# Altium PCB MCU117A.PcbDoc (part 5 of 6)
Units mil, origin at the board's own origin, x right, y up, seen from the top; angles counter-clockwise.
Board outline 2300 x 6749.64 mil, 6 copper layers (Top Signal, GND, Middle Signal, PWR, GND2, Bottom Signal), stack 61.64 mil thick; 424 components, 343 nets, 1563 pads, 921 vias.
Unrouted connection lines stored in the file: 4.
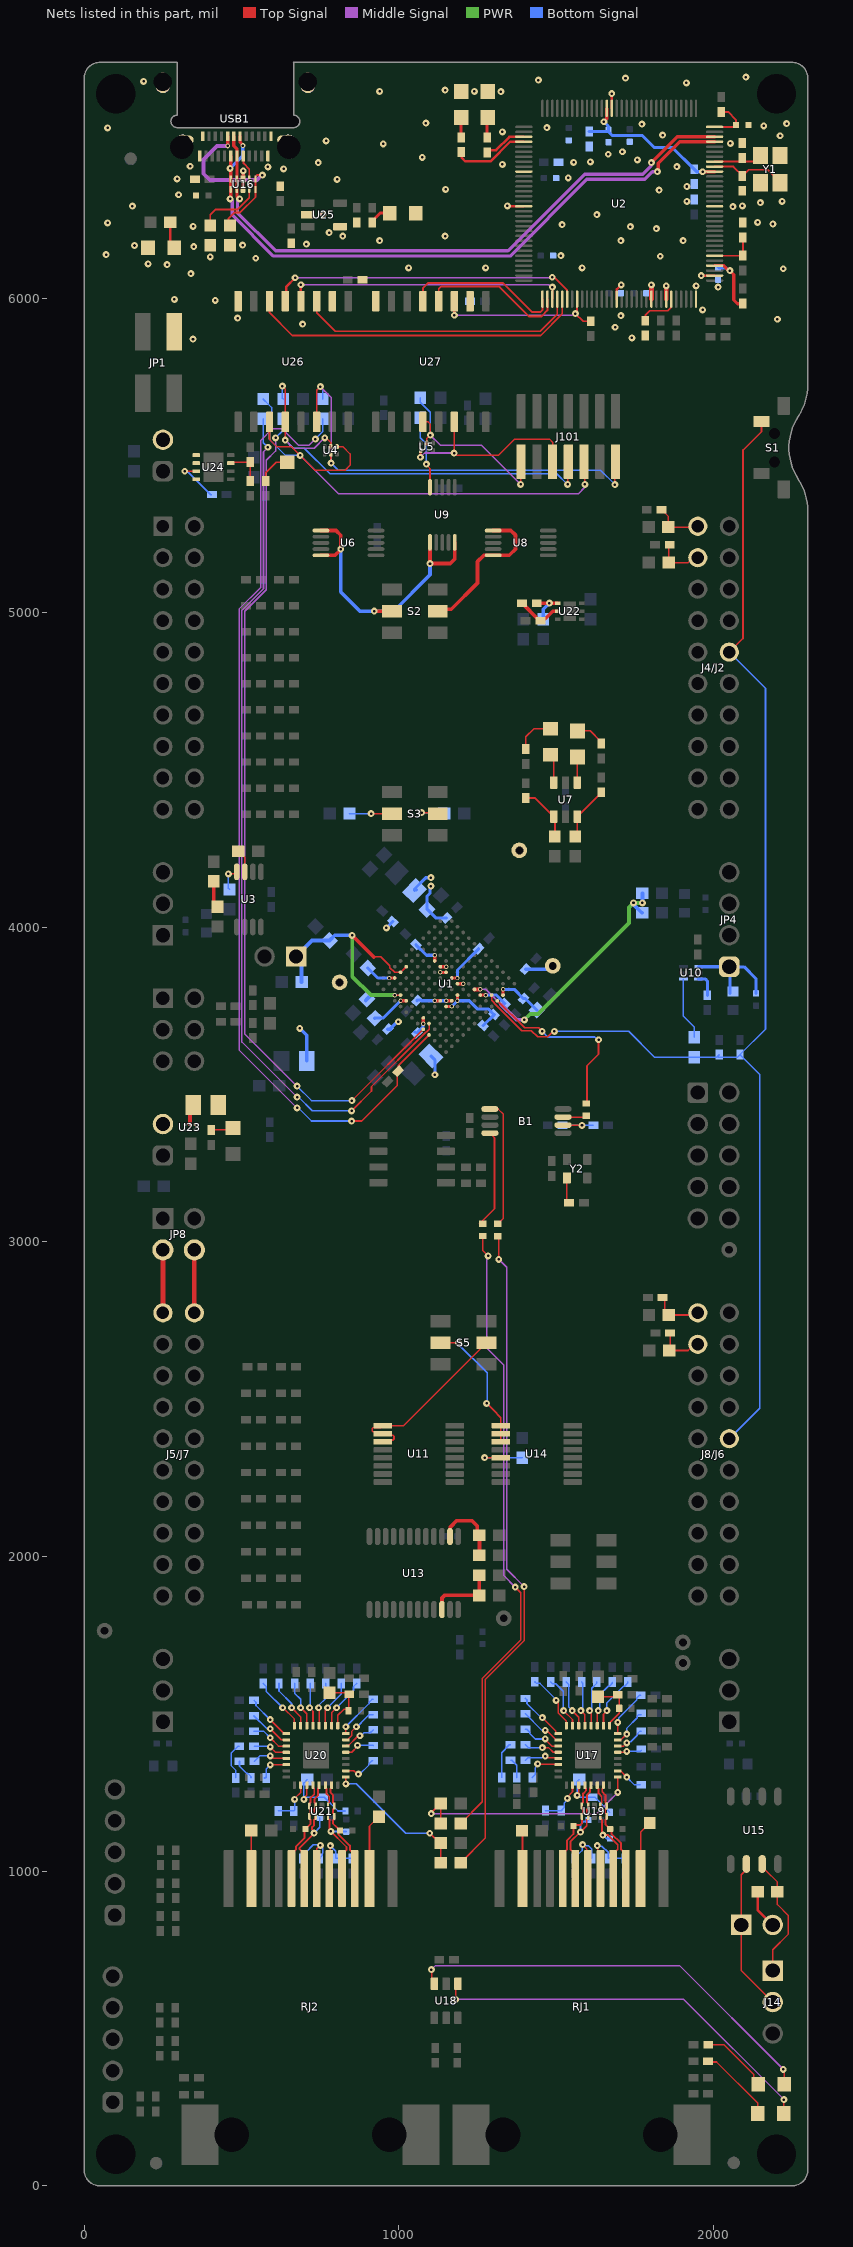
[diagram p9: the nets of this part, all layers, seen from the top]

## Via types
v1: diameter 22, hole 8, Top Signal to Bottom Signal, tented both sides, 821 vias
v2: diameter 14, hole 8, Top Signal to Bottom Signal, tented both sides, 82 vias
v3: diameter 19.68, hole 7.87, Top Signal to Bottom Signal, tented top, 14 vias
v4: diameter 15.75, hole 7.87, Top Signal to Bottom Signal, tented both sides, 2 vias
v5: diameter 19.68, hole 7.87, Top Signal to Bottom Signal, 2 vias

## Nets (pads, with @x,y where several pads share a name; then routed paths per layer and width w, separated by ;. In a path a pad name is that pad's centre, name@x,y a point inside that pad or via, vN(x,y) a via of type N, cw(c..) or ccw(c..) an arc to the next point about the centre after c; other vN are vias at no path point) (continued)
MCU_TDI: R99.1 U1.N9 | length 2754.5
  Top Signal w5: v1(850.28,3449.19) 850.83,3449.19 U1.N9@1077.57,3675.93
  Middle Signal w5: v1(608.14,5555.59) 608.14,5513.85 578.63,5484.34 578.63,5072.64 510.11,5004.11 510.11,3661.22 v1(676.18,3495.14)
  Bottom Signal w5: v1(608.14,5555.59) 632.11,5579.55 R99.1@632.11,5616.01 ; v1(676.18,3495.14) 722.13,3449.19 v1(850.28,3449.19)
MCU_TDI_INT: J101.8 R99.2 U4.5 U26.12 | length 1436.3
  Top Signal w5: v1(629.53,5720.16) 638.77,5710.92 v1(638.77,5548.46) ; v1@764.28,5560 783.64,5540.64 U4.5@783.64,5527.8 ; v1(1535.98,5407.41) 1535.98,5477.01 J101.8@1538.46,5479.49
  Middle Signal w5: v1(638.77,5548.46) 664.31,5522.92 730.89,5522.92 763.56,5555.59 v1(764.29,5555.59)
  Bottom Signal w5: v1(629.53,5720.16) 629.53,5681.57 R99.2@632.11,5679 ; v1(638.77,5548.46) 664.31,5522.92 699.57,5522.92 781.1,5441.4 1501.99,5441.4 v1(1535.98,5407.41)
MCU_TDO: R100.1 U1.M9 | length 2839.5
  Top Signal w4: 1077.57,3658.38 1095.67,3676.48 U1.M9@1095.67,3694.02
  Top Signal w5: v1(849.98,3416.58) 913.01,3479.6 913.01,3493.82 1077.57,3658.38
  Middle Signal w5: v1(583.65,5525.58) 569.63,5511.57 569.63,5076.37 501.11,5007.84 501.11,3635.5 v1(676.18,3460.43)
  Bottom Signal w5: R100.1@569.11,5616.01 569.11,5540.13 v1(583.65,5525.58) ; v1(676.18,3460.43) 680.61,3460.43 724.46,3416.58 v1(849.98,3416.58)
MCU_TDO_INT: J101.6 R100.2 U4.4 U26.11 | length 1751.8
  Top Signal w5: U26.11@588.77,5606.07 588.77,5550.64 612.67,5526.73 659.19,5526.73 v1(686.22,5499.71) 733.3,5452.63 829.09,5452.63 844.81,5468.34 844.81,5504.17 821.18,5527.8 U4.4@803.33,5527.8 ; J101.6@1588.46,5479.49 1590.82,5477.12 v1@1590.82,5398.49
  Middle Signal w5: v1(686.22,5499.71) 807.8,5378.12 1570.45,5378.12 v1@1590.82,5398.49
  Bottom Signal w5: R100.2@569.11,5679 569.11,5678.02 585.31,5661.81 585.84,5661.81 595.31,5652.35 595.31,5593.22 588.77,5586.68 588.77,5550.64 639.7,5499.71 v1(686.22,5499.71)
  other v1: 1590.82,5407.41
MCU_TMS: R44.1 R97.1 U1.N10 | length 3103.8
  Top Signal w4: R44.1@997.83,3542.69 997.83,3560 U1.N10@1095.67,3657.83
  Top Signal w5: v1(849.58,3384.3) 881.97,3384.3 995.35,3497.67 R44.1@995.35,3542.69
  Middle Signal w5: v1(676.18,3425.71) 492.11,3609.79 492.11,5011.57 560.63,5080.09 560.63,5547.11 598.55,5585.04 627.73,5585.04 680.85,5531.92 714.63,5531.92 v1(734.38,5551.67)
  Bottom Signal w5: v1(676.18,3425.71) 680.61,3425.71 722.02,3384.3 v1(849.58,3384.3) ; v1(734.38,5551.67) 758.11,5575.39 R97.1@758.11,5616.01
MCU_TMS_INT: J101.2 R97.2 U4.2 U26.14 | length 1450.3
  Top Signal w5: U26.14@738.77,5606.07 738.77,5706.78 v1(750.34,5718.35) ; U4.2@783.64,5504.17 783.64,5476.02 v1(784.69,5474.98) ; v1(1686.58,5406.94) 1686.58,5477.61 J101.2@1688.46,5479.49
  Middle Signal w5: v1(750.34,5718.35) 784.69,5684 v1(784.69,5474.98)
  Bottom Signal w5: v1(750.34,5718.35) 758.11,5710.58 R97.2@758.11,5679 ; v1(784.69,5474.98) 807.26,5452.41 1641.11,5452.41 v1(1686.58,5406.94)
MCU_TXD: R171.1 U9.10 | length 234
  Top Signal w5: v1(1087.05,5472.39) 1087.05,5469.75 1098.81,5457.99 U9.10@1098.81,5398.49
  Bottom Signal w5: R171.1@1068.17,5619.76 1068.17,5556.14 1087.05,5537.26 v1(1087.05,5472.39)
MCU_TXD_INT: J101.14 R171.2 U5.5 U27.12 | length 648.2
  Top Signal w5: U27.12@1076.45,5606.07 1093.63,5606.07 1099.88,5599.81 v1(1099.88,5564.14) 1088.9,5553.15 U5.5@1088.9,5538.62 ; v1(1387,5407.41) 1387,5478.03 J101.14@1388.46,5479.49
  Middle Signal w5: v1(1099.88,5564.14) 1131.52,5532.5 1261.91,5532.5 v1(1387,5407.41)
  Bottom Signal w5: R171.2@1068.17,5682.75 1068.17,5668.75 1099.88,5637.03 v1(1099.88,5564.14)
NetB1_2: B1.2 R24.2 R26.2 | length 153.9
  Top Signal w5: B1.2@1521.54,3371.33 1580.98,3371.33 v1(1581.94,3370.36)
  Bottom Signal w5: R26.2@1524.71,3370.36 v1(1581.94,3370.36) R24.2@1617.86,3370.36
NetB1_3: B1.3 R20.1 | length 63.3
  Top Signal w5: B1.3@1535.8,3395.95 1587.25,3395.95 R20.1@1595.63,3404.34
NetB1_5: B1.5 R22.1 | length 405.1
  Top Signal w5: B1.5@1289.26,3422.51 1315.26,3422.51 1332.16,3405.61 1332.16,3075.29 R22.1@1314.54,3057.67
NetB1_8: B1.8 R21.1 | length 314
  Top Signal w5: R21.1@1255.95,3057.67 1303.89,3105.61 1303.89,3331.11 B1.8@1289.26,3345.74
NetC1_1: C1.1 J4/J2.39 R2.1 | length 156.9
  Top Signal w5: C1.1@1860.91,5215.41 1857.45,5211.95 1857.45,5167.36 R2.1@1857.45,5158.98 1919.17,5158.98 1934.83,5174.64 J4/J2.39@1949.99,5174.64
NetC2_1: C2.1 J4/J2.40 R1.1 | length 158.9
  Top Signal w5: C2.1@1834.95,5327.3 1856.61,5305.65 R1.1@1856.61,5271.89 1947.24,5271.89 J4/J2.40@1949.99,5274.64
NetC3_1: C3.1 J8/J6.80 R3.1 | length 158.4
  Top Signal w5: C3.1@1838.31,2823.34 1845.24,2816.41 1845.24,2780.65 R3.1@1857.99,2767.89 1943.24,2767.89 J8/J6.80@1949.99,2774.64
NetC4_1: C4.1 J8/J6.79 R4.1 | length 152.8
  Top Signal w5: R4.1@1859.01,2655 1862.24,2658.23 C4.1@1862.24,2710.54 ; R4.1@1862.24,2655 1918.8,2655 1938.45,2674.64 J8/J6.79@1949.99,2674.64
NetC52_1: C52.1 R66.1 | length 77.4
  Top Signal w12: C52.1@411.27,4137.33 411.27,4081.81 424.62,4068.46 R66.1@424.62,4065.51
NetC53_1: C53.1 U3.4 | length 80.3
  Top Signal w5: v1(458.02,4169.71) 477.88,4169.71 U3.4@484.52,4176.35
  Bottom Signal w5: v1(458.02,4169.71) 458.02,4124.11 C53.1@461.88,4120.25
NetC87_2: C87.2 C88.2 RJ1.5 | length 225
  Top Signal w5: v1(1630.52,1081.53) 1631.86,1080.19 1631.86,985.5 RJ1.5@1640.79,976.57
  Bottom Signal w4: v1(1630.52,1081.53) 1632.05,1080 1645.03,1080 1665.01,1060.03 1665.01,1042.6 C88.2@1666.99,1040.62 C87.2@1719.18,1040.62
NetC89_1: C89.1 C90.1 U17.2 | length 142.6
  Top Signal w5: v1(1535.78,1231.61) 1535.78,1236.21 1551.78,1252.21 U17.2@1551.78,1270.27
  Bottom Signal w5: C89.1@1465.98,1192.38 C90.1@1515.72,1192.38 1525.04,1201.69 1525.04,1216.27 1535.78,1227.01 v1(1535.78,1231.61)
NetC95_2: C95.2 C96.2 RJ1.6 | length 232.5
  Top Signal w5: v1(1583.95,1084.27) 1596.53,1071.69 1596.53,980.68 RJ1.6@1600.64,976.57
  Bottom Signal w5: C96.2@1560.99,1040.62 1560.99,1044.56 1582.2,1065.77 1582.2,1082.51 v1(1583.95,1084.27) 1587,1081.22 1602.45,1081.22 1612.99,1070.68 C95.2@1612.99,1040.62
NetC97_1: C97.1 C98.1 R131.2 U17.3 | length 214.8
  Top Signal w4: v1(1566.18,1241) 1571.46,1246.29 U17.3@1571.46,1273.71
  Bottom Signal w5: C97.1@1572.73,1291.13 1566.18,1284.58 v1(1566.18,1241) 1572.51,1234.67 C98.1@1615.91,1234.67 1622.93,1234.67 R131.2@1670.78,1186.82
NetC99_1: C99.1 C100.1 R134.1 U17.17 | length 176.8
  Top Signal w5: C99.1@1633.17,1554.85 1689.95,1554.85 C100.1@1695.49,1560.38 1700.18,1555.69 R134.1@1700.18,1517.82 1700.18,1502.13 1669.89,1471.84 U17.17@1669.89,1462.69
NetC102_2: C102.2 C104.2 RJ2.5 | length 206
  Top Signal w4: RJ2.5@779.08,976.57 782.11,979.6 v1(782.11,1081.08)
  Bottom Signal w5: v1(782.11,1081.08) 799.42,1063.77 C104.2@799.42,1040.62 C102.2@852,1040.62
NetC105_1: C105.1 C106.1 U20.2 | length 139.9
  Top Signal w5: v1(668.56,1228.43) 668.56,1231.02 687.82,1250.28 687.82,1273.53 U20.2@687.63,1273.71
  Bottom Signal w5: C105.1@617,1191.97 C106.1@666,1191.97 668.56,1194.53 v1(668.56,1228.43)
NetC111_2: C111.2 C112.2 RJ2.6 | length 238.8
  Top Signal w4: RJ2.6@738.92,976.57 738.92,1070.86 v1(750.16,1082.1)
  Bottom Signal w5: C112.2@695,1040.62 703.83,1049.46 703.83,1059.83 727.72,1083.72 748.54,1083.72 v1(750.16,1082.1) 750.16,1081.08 757.49,1073.75 757.49,1056.71 756.81,1056.04 756.81,1050.43 C111.2@747,1040.62
NetC113_1: C113.1 C114.2 R166.2 U20.3 | length 268.6
  Top Signal w5: v1(698.18,1228.43) 698.18,1233.3 707.32,1242.44 U20.3@707.32,1273.71
  Bottom Signal w5: C113.1@708.65,1291.13 698.18,1280.66 v1(698.18,1228.43) 704.57,1234.83 762.78,1234.83 806.21,1191.4 R166.2@830.05,1191.4
NetC115_1: C115.1 C116.2 R168.1 U20.17 | length 194.7
  Top Signal w4: R168.1@840.21,1510.09 840.21,1517.22 840.21,1557.91 C116.2@842.32,1560.03
  Top Signal w5: C115.1@779.1,1567.08 837.96,1567.08 C116.2@842.32,1562.72 C116.2@842.32,1560.03 ; U20.17@805.74,1462.69 805.74,1495.33 825.35,1514.94 837.92,1514.94 R168.1@840.21,1517.22
NetC123_1: C123.1 U24.3 | length 152.7
  Top Signal w4: v1(319.48,5449.51) U24.3@355.62,5449.51
  Bottom Signal w4: v1(319.48,5449.51) 322.92,5446.06 330.86,5446.06 401.43,5375.49 C123.1@405.37,5375.49
NetC125_1: C125.1 U10.3 | length 76.8
  Bottom Signal w10: U10.3@1951.62,3835.32 1974.65,3835.32 1980.51,3829.46 C125.1@1980.51,3783.93
NetC131_2: C131.2 R164.2 U2.96 | length 144.3
  Top Signal w6: U2.96@2003.34,6543.74 2065.55,6543.74 C131.2@2071.32,6549.5 2071.32,6566.3 2046.24,6591.38 R164.2@2024.59,6591.38
NetC142_1: C142.1 C143.2 C144.1 U2.87 U2.115 | length 531.6
  Top Signal w10: v1(1651.4,6560.23) 1660.82,6569.65 U2.115@1660.82,6602.79 ; v1(1965.27,6401.41) U2.87@2003.93,6401.41
  Bottom Signal w10: C144.1@1604.32,6529.43 C143.2@1661.18,6529.43 ; v1(1651.4,6560.23) 1666.29,6545.33 C143.2@1666.29,6534.55 1666.29,6528.4 1678.15,6516.54 1773.25,6516.54 1811.38,6478.42 1869.21,6478.42 C142.1@1938.48,6409.14 1946.21,6401.41 v1(1965.27,6401.41)
NetC145_2: C145.2 R177.1 U2.68 | length 230.3
  Top Signal w10: U2.68@2003.34,6102.79 2032.75,6102.79 2048.5,6087.04 v1(2051.75,6087.04) 2064.13,6074.66 2064.13,5993.66 2076.17,5981.61 R177.1@2093.65,5981.61
  Bottom Signal w10: C145.2@2014.52,6099.37 2017.78,6096.11 2039.43,6096.11 2048.5,6087.04 v1(2051.75,6087.04)
NetC146_1: C146.1 U2.89 Y1.3 | length 153.4
  Top Signal w6: U2.89@2003.34,6433.5 2129.24,6433.5 Y1.3@2148.69,6452.95
NetC147_1: C147.1 U2.88 Y1.1 | length 249.7
  Top Signal w6: U2.88@2003.34,6417.75 2063.14,6417.75 2094.01,6386.89 2094.01,6389.72 2111.84,6407.56 2172.57,6407.56 2211.69,6368.44 Y1.1@2211.69,6366.33
NetD11_1: D11.1 U18.6 | length 1358.4
  Top Signal w5: v1(1103,687) 1104.26,685.74 1104.26,650.55 U18.6@1112.82,641.99 ; v1(2221.58,370.21) 2224.65,367.15 D11.1@2224.65,322.85
  Middle Signal w5: v1(1103,687) 1116.12,700.12 1891.68,700.12 v1(2221.58,370.21)
NetD11_2: D11.2 R137.1 | length 220.7
  Top Signal w5: R137.1@1983.1,448.55 2032.96,448.55 2127.82,353.68 2127.82,337 D11.2@2141.97,322.85
NetD12_1: D12.1 U18.4 | length 1271.1
  Top Signal w5: v1(1180.62,592.91) 1180.62,634.99 U18.4@1187.62,641.99 ; v1(2223.58,274.21) 2223.58,230.14 D12.1@2223.65,230.08
  Middle Signal w5: v1(1180.62,592.91) 1904.88,592.91 v1(2223.58,274.21)
NetD12_2: D12.2 R138.2 | length 245.7
  Top Signal w5: R138.2@1982.94,396.16 1985.54,393.56 2009.72,393.56 2140.97,262.31 D12.2@2140.97,230.08
NetJ5/J7_41: J5/J7.41 JP8.3 | length 200
  Top Signal w15: J5/J7.41@249.99,2774.64 JP8.3@249.99,2974.64
NetJ5/J7_61: J5/J7.61 JP8.4 | length 200
  Top Signal w15: J5/J7.61@349.99,2774.64 JP8.4@349.99,2974.64
NetJ14_1: J14.1 R11.2 U15.7 | length 396.1
  Top Signal w5: U15.7@2154.49,1023.02 2154.49,1010.52 2161.71,1003.3 2165.04,1003.3 2202.99,965.35 R11.2@2202.99,934.65 2202.99,893.86 2237.99,858.85 2237.99,800.31 2188.29,750.61 J14.1@2188.29,684.07
NetJ14_2: J14.2 JP9.1 U15.6 | length 487.3
  Top Signal w5: U15.6@2104.49,1023.02 2104.49,1005.62 2087.99,989.12 JP9.1@2087.99,829.31 2087.99,684.36 J14.2@2188.29,584.07
NetJ16_2: J16.2 U24.1 U24.2 U24.4
NetJ17_2: J17.2 L4.1 U23.A1 U23.C1
NetJP9_2: JP9.2 R11.1 | length 125.2
  Top Signal w8: R11.1@2140,934.65 2140,877.31 JP9.2@2187.99,829.31
NetL4_2: L4.2 U23.B1 | length 66.5
  Top Signal w6: L4.2@335.75,3424.75 L4.2@346,3435
  Top Signal w12: U23.B1@335.75,3372.75 L4.2@335.75,3424.75
NetLED1_2: LED1.2 R69.1 | length 85.6
  Top Signal w8: R69.1@273.63,6240.51 273.63,6171.56 LED1.2@285.43,6159.76
NetLED3_2: LED3.2 R82.1 | length 71.2
  Top Signal w5: R82.1@396,3356.62 463.56,3356.62 LED3.2@466.15,3359.21
NetLED4_1: LED4.1 U7.6 | length 92.8
  Top Signal w5: LED4.1@1482.15,4548.47 1492.15,4538.47 U7.6@1492.15,4459.8
NetLED4_2: LED4.2 R12.1 | length 128
  Top Signal w5: R12.1@1403.55,4566.77 1403.55,4605.65 1429.06,4631.15 LED4.2@1482.15,4631.15
NetLED5_1: LED5.1 R13.1 | length 88.7
  Top Signal w5: LED5.1@1568.2,4624.45 1607.88,4624.45 R13.1@1642.55,4589.77
NetLED5_2: LED5.2 U7.4 | length 82.5
  Top Signal w5: U7.4@1566.96,4459.8 1566.96,4540.53 LED5.2@1568.2,4541.77
NetLED6_2: LED6.2 R90.2 | length 107.9
  Top Signal w5: R90.2@576.92,5418.89 576.92,5444.48 610.5,5478.07 LED6.2@645.34,5478.07
NetLED7_2: LED7.2 R96.2 | length 68.8
  Top Signal w10: R96.2@910.18,6239.81 940.77,6270.39 LED7.2@966.33,6270.39
NetLED8_1: LED8.1 R172.1 | length 64.5
  Top Signal w10: R172.1@1280.25,6509.98 1280.25,6571.67 LED8.1@1282.24,6573.66
NetLED9_1: LED9.1 R173.1 | length 67.9
  Top Signal w10: R173.1@1197.5,6510.79 1197.5,6572.8 LED9.1@1197.99,6573.3 LED9.1@1201.64,6569.65
NetR14_1: R14.1 R17.2 U7.1 | length 177.4
  Top Signal w6: R14.1@1403.55,4410.52 1433.16,4410.52 U7.1@1492.15,4351.53 1495.63,4348.05 R17.2@1495.63,4288.61
NetR15_1: R15.1 R19.2 U7.3 | length 174.8
  Top Signal w6: R19.2@1560.53,4288.61 1566.96,4295.03 U7.3@1566.96,4351.53 1643.14,4427.72 R15.1@1643.14,4429.14
NetR23_2: R23.2 Y2.1 | length 81.6
  Top Signal w5: Y2.1@1533.71,3203.46 1533.71,3131.76 R23.2@1540.7,3124.77
NetR30_1: R30.1 R35.2 U13.2 | length 227.1
  Top Signal w12: U13.2@1162.44,2063.9 1163.53,2064.99 1163.53,2094.09 1183.37,2113.92 1232.6,2113.92 1248.86,2097.66 1248.86,2075.03 R35.2@1255.9,2067.99 R30.1@1255.9,2004.39
NetR31_2: R31.2 S3.5 | length 135.1
  Top Signal w5: v1(911.88,4361.28) S3.5@977.96,4361.28
  Bottom Signal w5: R31.2@842.9,4361.28 v1(911.88,4361.28)
NetR33_1: R33.1 S3.2 | length 126.7
  Top Signal w5: v1(1072.15,4364.56) 1120.34,4364.56 S3.2@1123.63,4361.28
  Bottom Signal w5: v1(1072.15,4364.56) 1141.34,4364.56 R33.1@1144.63,4361.28
NetR34_1: R34.1 R36.1 U13.22 | length 222
  Top Signal w12: U13.22@1136.85,1831.61 1136.85,1868.22 1146.01,1877.39 1255.47,1877.39 R34.1@1255.47,1940.4
NetR37_1: R37.1 U14.13 | length 171.6
  Top Signal w5: v1(1272.44,2314.41) 1272.8,2314.05 1323.8,2314.05 U14.13@1324.16,2313.69
  Bottom Signal w5: v1(1272.44,2314.41) 1391.06,2314.41 R37.1@1391.77,2313.69
NetR58_1: R58.1 U17.23 | length 173.6
  Top Signal w5: v1(1523.5,1510.14) 1551.78,1481.86 U17.23@1551.78,1462.69
  Bottom Signal w5: R58.1@1482.44,1601.46 1488.41,1595.49 1498.82,1595.49 1522.6,1571.71 1522.6,1525.85 1522.82,1525.63 1522.82,1510.82 v1(1523.5,1510.14)
NetR67_2: R67.2 U3.3 | length 74.2
  Top Signal w5: R67.2@489.76,4241.58 490.74,4241.58 510.11,4222.21 U3.3@510.11,4176.35
NetR70_2: R70.2 R72.2 U22.1 | length 126.6
  Top Signal w12: R72.2@1437.98,5030.23 U22.1@1504.83,5030.23
  Bottom Signal w12: R70.2@1458.73,4979.14 1458.73,5010.76 v1(1478.59,5030.63)
NetR72_1: R72.1 R79.2 U22.2 | length 145.5
  Top Signal w12: R72.1@1390.74,5030.23 1441.92,4979.05 R79.2@1447.68,4979.05 ; R79.2@1449.8,4974.86 1455.61,4980.67 1465.16,4980.67 1489.13,5004.64 U22.2@1504.83,5004.64
NetR83_1: R83.1 U17.27 | length 130
  Top Signal w5: v1@1464.93,1420.54 1464.93,1418.46 1485.67,1397.73 U17.27@1506.5,1397.73
  Bottom Signal w5: R83.1@1402.34,1451.08 1406.28,1451.08 1415.59,1441.77 1415.59,1437.83 1433.17,1420.25 v1(1465.03,1420.25)
NetR84_1: R84.1 U17.26 | length 137.6
  Top Signal w5: v1@1465.03,1445.51 1467.33,1443.21 1473.81,1443.21 1499.61,1417.41 U17.26@1506.5,1417.41
  Bottom Signal w5: R84.1@1402.34,1500.15 1455.04,1447.45 v1(1465.03,1447.45)
NetR85_1: R85.1 R94.2 U24.7 | length 122.2
  Top Signal w5: U24.7@465.86,5475.1 469.1,5478.34 R94.2@527.12,5478.34 527.12,5419.36 R85.1@527.58,5418.89
NetR86_1: R86.1 U17.25 | length 160.7
  Top Signal w5: v1(1455.97,1488.21) 1498.7,1445.48 1498.7,1439.52 1501.12,1437.1 U17.25@1506.5,1437.1
  Bottom Signal w5: R86.1@1402.34,1548.91 1407.15,1544.11 1407.15,1532.53 1451.47,1488.21 v1(1455.97,1488.21)
NetR87_1: R87.1 U17.24 | length 187.4
  Top Signal w5: v1(1499.61,1542.74) 1506.3,1536.06 1506.3,1503.02 1532.09,1477.22 U17.24@1532.09,1462.69
  Bottom Signal w5: R87.1@1432.06,1602.22 1437.43,1596.85 1448.44,1596.85 1499.61,1545.68 v1(1499.61,1542.74)
NetR91_1: R91.1 U20.23 | length 162.4
  Top Signal w5: v1(659.21,1519.64) 687.63,1491.22 U20.23@687.63,1462.69
  Bottom Signal w5: R91.1@618.85,1596.61 618.85,1572.73 659.21,1532.37 v1(659.21,1519.64)
NetR92_1: R92.1 U20.27 | length 122.8
  Top Signal w5: v1(591.04,1424.06) 617.37,1397.73 U20.27@642.35,1397.73
  Bottom Signal w5: R92.1@539.37,1445.51 569.59,1445.51 v1(591.04,1424.06)
NetR95_2: R95.2 U10.4 | length 199.3
  Bottom Signal w5: U10.4@1904.38,3835.32 1904.38,3717.52 1938.83,3683.07 R95.2@1938.83,3650.29
NetR108_1: R108.1 U17.21 | length 147
  Top Signal w5: v1(1578.57,1510.14) 1591.15,1497.57 U17.21@1591.15,1462.69
  Bottom Signal w5: R108.1@1580.66,1601.39 1584.43,1597.63 1584.43,1520.6 1581.83,1518 1581.83,1513.42 v1@1584.43,1510.81
NetR109_2: R109.2 U17.10 | length 93.7
  Top Signal w5: U17.10@1695.48,1318.99 1704.06,1318.99 v1(1724.25,1298.8) v1@1727.43,1298.8
  Bottom Signal w5: v1(1724.25,1298.8) 1748.73,1274.32 R109.2@1767.5,1274.32
NetR110_1: R110.1 U20.26 | length 135.3
  Top Signal w5: v1(591.04,1452.8) 626.42,1417.41 U20.26@642.35,1417.41
  Bottom Signal w5: R110.1@538.92,1494.37 580.49,1452.8 v1(591.04,1452.8)
NetR114_2: R114.2 U17.19 | length 159.1
  Top Signal w5: U17.19@1630.52,1462.69 1630.52,1507.01 v1(1633.65,1510.14)
  Bottom Signal w5: v1@1637.32,1510.14 1637.92,1510.75 1637.92,1560.63 1665.17,1587.87 1669.11,1587.87 1678.42,1597.18 R114.2@1678.42,1601.12
NetR115_2: R115.2 U17.18 | length 172.8
  Top Signal w5: U17.18@1650.2,1462.69 1650.2,1499.16 v1(1661.19,1510.14)
  Bottom Signal w5: v1(1661.19,1510.14) 1661.19,1535.8 1713.6,1588.22 1717.54,1588.22 1726.85,1597.53 R115.2@1726.85,1601.47
NetR116_2: R116.2 U17.15 | length 122.9
  Top Signal w5: U17.15@1695.48,1417.41 1706.19,1417.41 v1(1724.25,1435.47) ; v1@1723.08,1436.64 v1@1723.54,1437.1
  Bottom Signal w5: v1(1724.25,1435.47) 1724.8,1436.02 1724.8,1454.98 1757.36,1487.54 1757.36,1493.38 1760.61,1496.63 R116.2@1770.38,1496.63
NetR117_2: R117.2 U17.14 | length 97.1
  Top Signal w5: U17.14@1695.48,1397.73 1713.84,1397.73 v1(1724.25,1408.14)
  Bottom Signal w5: v1(1724.25,1408.14) 1727.5,1411.39 1736.52,1411.39 1757.13,1432 1757.13,1436.29 1766.1,1445.25 R117.2@1770.38,1445.25
NetR118_2: R118.2 U17.13 | length 77.3
  Top Signal w5: U17.13@1695.48,1378.04 1721.49,1378.04 v1(1724.25,1380.8)
  Bottom Signal w5: v1(1724.25,1380.8) 1767.39,1380.8 R118.2@1770.38,1383.79
NetR119_2: R119.2 U17.20 | length 147.9
  Top Signal w5: v1(1606.11,1510.14) 1610.83,1505.42 U17.20@1610.83,1462.69
  Bottom Signal w5: v1@1612.88,1510.11 1612.88,1581.47 1629.28,1597.88 R119.2@1629.28,1601.81
NetR120_2: R120.2 U17.22 | length 155.4
  Top Signal w5: v1(1551.03,1510.14) 1571.46,1489.71 U17.22@1571.46,1462.69
  Bottom Signal w5: R120.2@1531.6,1601.53 1539.54,1593.58 1539.54,1521.63 v1(1551.03,1510.14)
NetR121_1: R121.1 R123.2 | length 118.7
  Bottom Signal w4: R123.2@1326.23,1297.67 1326.23,1377.15 1351.16,1402.08 R121.1@1355.1,1402.08
NetR121_2: R121.2 U17.28 | length 114.1
  Top Signal w5: v1(1456.01,1393.06) 1475.28,1393.06 1490.3,1378.04 U17.28@1506.5,1378.04
  Bottom Signal w5: R121.2@1402.34,1402.08 1411.36,1393.06 v1(1456.01,1393.06)
NetR122_1: R122.1 R124.2 | length 65.2
  Bottom Signal w5: R122.1@1355.1,1352.41 1359.04,1352.41 1374.77,1336.67 R124.2@1374.77,1297.67
NetR122_2: R122.2 U17.29 | length 111.9
  Top Signal w5: v1@1464.6,1362.55 1466.7,1360.45 1504.41,1360.45 U17.29@1506.5,1358.36
  Bottom Signal w5: R122.2@1402.34,1352.41 1411.11,1361.17 1455.74,1361.17 1460.43,1365.87 v1(1465.03,1365.87)
NetR125_2: R125.2 U17.30 | length 116.9
  Top Signal w5: v1(1441,1340.94) 1442.14,1339.81 1505.37,1339.81 U17.30@1506.5,1338.67
  Bottom Signal w5: R125.2@1423.6,1297.67 1432.91,1306.98 1432.91,1328.25 1441,1336.34 v1(1441,1340.94)
NetR126_2: R126.2 U17.16 | length 155
  Top Signal w5: U17.16@1695.48,1437.1 v1(1695.48,1473.1)
  Bottom Signal w5: v1(1695.48,1473.1) 1698.21,1475.83 1698.21,1486.54 1755.99,1544.32 1755.99,1550.47 1765.3,1559.78 R126.2@1768.69,1559.78
NetR132_2: R132.2 RJ1.11 | length 152.5
  Top Signal w5: R132.2@1391.14,1128.4 1392.76,1126.78 RJ1.11@1392.76,976.57
NetR135_2: R135.2 RJ1.2 | length 188.5
  Top Signal w5: RJ1.2@1768.35,976.57 1768.35,1124.55 R135.2@1797.04,1153.23
NetR142_1: R142.1 U20.21 | length 129.3
  Top Signal w5: v1(716.3,1519.64) 727,1508.94 U20.21@727,1462.69
  Bottom Signal w5: v1@717.94,1528.7 R142.1@717.94,1596.61
NetR143_2: R143.2 U20.10 | length 109.6
  Top Signal w5: U20.10@831.33,1318.99 856.29,1318.99 866.54,1308.74 v1(871.14,1308.74)
  Bottom Signal w5: v1(871.14,1308.74) 875.56,1308.74 904.63,1337.82 904.63,1341.38 913.73,1350.48 R143.2@917.29,1350.48
NetR144_1: R144.1 U20.25 | length 152.4
  Top Signal w5: v1@590.79,1481.53 v1(591.04,1481.53) 635.46,1437.1 U20.25@642.35,1437.1
  Bottom Signal w5: R144.1@539.75,1542.86 545.84,1536.76 545.84,1526.48 v1@590.79,1481.53
NetR148_2: R148.2 U20.19 | length 154.8
  Top Signal w5: U20.19@766.37,1462.69 766.37,1512.62 v1(773.39,1519.64)
  Bottom Signal w5: v1(773.39,1519.64) 816.71,1562.97 R148.2@816.71,1596.61
NetR149_2: R149.2 U20.18 | length 166.8
  Top Signal w5: U20.18@786.06,1462.69 786.06,1503.76 v1(801.94,1519.64)
  Bottom Signal w5: v1(801.94,1519.64) 855.64,1573.35 855.64,1586.8 R149.2@865.45,1596.61
NetR150_2: R150.2 U20.15 | length 127.8
  Top Signal w5: U20.15@831.33,1417.41 836.42,1417.41 849.64,1430.64 849.64,1443.67 v1(865.04,1459.07)
  Bottom Signal w5: v1(865.04,1459.07) 867.3,1459.07 894,1485.76 905.62,1497.38 R150.2@918.38,1497.38
NetR151_1: R151.1 U20.30 | length 103
  Top Signal w5: v1(591.04,1337.87) 641.56,1337.87 U20.30@642.35,1338.67
  Bottom Signal w5: R151.1@572.81,1296.19 574.41,1296.19 R151.1@577.03,1298.81 ; R151.1@579,1296.84 579,1325.84 v1(591.04,1337.87)
NetR152_2: R152.2 U20.14 | length 108.3
  Top Signal w5: U20.14@831.33,1397.73 833.18,1399.58 840.07,1399.58 867.88,1427.38 872.5,1427.38 v1(875.75,1430.64)
  Bottom Signal w5: v1(875.75,1430.64) 880.35,1430.64 889.37,1439.66 909.07,1439.66 R152.2@918.38,1448.97
NetR153_2: R153.2 U20.13 | length 98.5
  Top Signal w5: U20.13@831.33,1378.04 850.27,1378.04 868.4,1396.18 v1(868.4,1399.99)
  Bottom Signal w5: v1(868.4,1399.99) 917.96,1399.99 R153.2@918.38,1399.57
NetR154_2: R154.2 U20.20 | length 144
  Top Signal w5: v1(744.85,1519.64) 746.69,1517.8 U20.20@746.69,1462.69
  Bottom Signal w5: v1(744.85,1519.64) 744.85,1526.43 767.33,1548.91 R154.2@767.33,1596.61
NetR155_2: R155.2 U20.22 | length 150
  Top Signal w5: v1(687.75,1519.64) 707.32,1500.08 U20.22@707.32,1462.69
  Bottom Signal w5: R155.2@668.56,1596.61 668.56,1566.01 687.75,1546.79 v1(687.75,1519.64)
NetR156_1: R156.1 R159.2 | length 118.5
  Bottom Signal w5: R159.2@481,1296.84 481,1321.46 467.79,1334.68 467.79,1376.31 488.75,1397.27 R156.1@492.68,1397.27
NetR156_2: R156.2 U20.28 | length 110.6
  Top Signal w5: v1@590.6,1394.9 607.45,1378.04 U20.28@642.35,1378.04
  Bottom Signal w5: R156.2@539.93,1397.27 589.1,1397.27 v1(591.04,1395.33)
NetR157_1: R157.1 R160.2 | length 69.6
  Bottom Signal w5: R157.1@493.38,1349 493.38,1333.46 516.25,1310.59 520.19,1310.59 530,1300.78 R160.2@530,1296.84
NetR157_2: R157.2 U20.29 | length 112.4
  Top Signal w5: v1(591.04,1366.6) 599.28,1358.36 U20.29@642.35,1358.36
  Bottom Signal w5: R157.2@540.62,1349 558.23,1366.6 v1(591.04,1366.6)
NetR158_2: R158.2 U20.16 | length 147.4
  Top Signal w5: U20.16@831.33,1437.1 v1(831.33,1459.07)
  Bottom Signal w5: v1(831.33,1459.07) 905.13,1532.87 905.13,1536.8 914.44,1546.11 R158.2@918.38,1546.11
NetR167_2: R167.2 RJ2.11 | length 153
  Top Signal w4: RJ2.11@531.05,976.57 R167.2@531.05,1129.58
NetR169_2: R169.2 RJ2.2 | length 209.6
  Top Signal w5: RJ2.2@906.64,976.57 906.64,1143.36 R169.2@936.93,1173.65
NetR172_2: R172.2 U2.3 | length 137.3
  Top Signal w7.87: R172.2@1280.25,6462.74 1287.81,6470.3 1309.1,6470.3 1351.04,6512.24 U2.3@1397.04,6512.24
NetR173_2: R173.2 U2.4 | length 251.2
  Top Signal w7.87: R173.2@1199.99,6469.01 1199.99,6445.15 1210.94,6434.21 1291.38,6434.21 1353.67,6496.49 U2.4@1397.04,6496.49
NetR174_1: R174.1 R175.2 U2.70 | length 146.6
  Top Signal w6: U2.70@2003.34,6134.29 2090.07,6134.29 2094.01,6130.35 2094.01,6134.29 R175.2@2094.01,6184.64
NetR176_2: R176.2 U2.59 | length 141.9
  Top Signal w6: R176.2@1783.91,5922.01 1783.91,5946.39 1796.97,5959.46 1854.33,5959.46 1865.54,5970.67 U2.59@1865.54,5996.49
NetR203_1: R203.1 U20.24 | length 175.6
  Top Signal w5: v1(630.66,1519.64) 631.85,1519.64 667.95,1483.54 U20.24@667.95,1462.69
  Bottom Signal w5: R203.1@568.95,1596.61 578.76,1586.8 578.76,1571.55 v1(630.66,1519.64)
PHY0_25MHZ_CLK: R21.2 R29.2 | length 1999.1
  Top Signal w5: R29.2@1196.24,1152.02 1264.84,1220.62 1264.84,1612.14 1387.63,1734.92 1387.63,1884.91 v1(1369.87,1902.67) ; R21.2@1265.92,3018.54 1265.92,2973.23 v1(1283.31,2955.83)
  Middle Signal w5: v1(1283.31,2955.83) 1279.8,2952.32 1279.8,2661.99 1333.87,2607.92 1333.87,1938.67 v1(1369.87,1902.67)
PHY0_CLK: R27.2 R29.1 U17.9 | length 777.6
  Top Signal w5: v1(1102.87,1183) 1102.87,1185.63 1132.26,1215.02 R27.2@1133.25,1215.02 R29.1@1133.25,1152.02 ; v1(1695.48,1250.42) U17.9@1695.48,1299.3
  Middle Signal w5: v1(1102.87,1183) 1628.06,1183 v1(1695.48,1250.42)
PHY0_RD_N: C93.1 RJ1.8 U17.4 U19.5 U19.6 | length 258.7
  Top Signal w5.91: RJ1.8@1520.32,1055.11 1534.4,1069.19 1534.4,1097.96 1554.91,1118.47 C93.1@1554.91,1143.35 1558.69,1147.13 1577.06,1147.13 1582.29,1152.36 1582.29,1173.89 U19.6@1581.62,1174.56 ; U19.6@1581.62,1181.75 1585.56,1185.69 1585.56,1196.31 1581.62,1200.25 1581.62,1214.62 1585.51,1218.51 1585.51,1246.84 1595.17,1256.5 1595.17,1262.8 1591.15,1266.82 U17.4@1591.15,1273.71
PHY0_RD_P: C94.1 RJ1.7 U17.5 U19.4 U19.7 | length 300.4
  Top Signal w5.91: RJ1.7@1555.95,1059.64 1545.31,1070.28 1545.31,1093.44 1576.43,1124.56 v1(1577.14,1124.56) ; v1@1576.57,1125.13 1577.39,1125.13 1596.92,1144.66 1596.92,1162.99 1601.31,1167.38 U19.7@1601.31,1174.56 ; U19.7@1601.31,1181.75 1597.37,1185.69 1597.37,1196.31 1601.31,1200.25 1601.31,1214.62 1597.42,1218.51 1597.42,1241.91 1607.08,1251.57 1607.08,1263.06 1610.83,1266.82 U17.5@1610.83,1273.71
  Bottom Signal w5.91: v1(1577.14,1124.56) 1577.14,1147.21 1588.19,1158.26 1598.41,1158.26 C94.1@1602.92,1162.77
PHY0_TD_N: C91.1 RJ1.4 U17.6 U19.2 U19.9 | length 374.4
  Top Signal w5.91: U17.6@1630.52,1273.71 1630.52,1266.82 1634.46,1262.88 1634.46,1247.36 1644.61,1237.2 1644.61,1218.56 1640.68,1214.62 U19.2@1640.68,1207.44 1640.68,1200.25 1644.85,1196.08 1644.85,1185.92 1640.68,1181.75 1640.68,1167.38 1641.66,1166.39 1642.05,1166.39 1645.51,1162.93 1645.51,1117.25 v1(1648.05,1114.71) 1664.68,1114.71 1695.51,1083.89 1695.51,1069.67 1680.95,1055.11 RJ1.4@1680.95,976.57
  Bottom Signal w5.91: v1(1648.05,1114.71) 1658.82,1103.94 C91.1@1671.19,1103.94
PHY0_TD_P: C92.1 RJ1.3 U17.7 U19.1 U19.10 | length 241.1
  Top Signal w5.91: U17.7@1650.2,1273.71 1650.2,1266.82 1646.27,1262.88 1646.27,1252.25 1656.43,1242.1 1656.43,1218.56 U19.1@1660.36,1214.62 ; U19.10@1660.36,1174.56 1660.36,1167.38 1656.42,1163.43 1656.42,1149.48 1675.33,1130.57 1675.33,1119.49 1706.42,1088.4 1706.42,1069.17 1711.42,1064.17 1716.12,1064.17 RJ1.3@1719.92,1060.36 ; U19.10@1660.36,1181.75 1659.38,1182.73 1659.21,1182.73 1655.76,1186.19 1655.76,1195.81 1659.21,1199.27 1659.38,1199.27 1660.36,1200.25 U19.1@1660.36,1207.44
PHY1_25MHZ_CLK: R22.2 R28.2 | length 2109.3
  Top Signal w5: R28.2@1196.24,1027.02 1273.84,1104.62 1273.84,1608.41 1397.88,1732.45 v1(1397.88,1904.83) ; R22.2@1314.54,3018.3 1317.46,3015.38 v1(1317.46,2944.7)
  Middle Signal w5: v1(1317.46,2944.7) 1342.87,2919.29 1342.87,1959.85 v1(1397.88,1904.83)
PHY1_CLK: R25.2 R28.1 U20.9 | length 464.3
  Top Signal w5: v1(831.33,1277.6) U20.9@831.33,1299.3 ; v1(1098.06,1120.65) 1128.69,1090.02 R25.2@1133.25,1090.02 R28.1@1133.25,1027.02
  Bottom Signal w5: v1(831.33,1277.6) 864.49,1277.6 1021.43,1120.65 v1(1098.06,1120.65)
PHY1_RD_N: C109.1 RJ2.8 U20.4 U21.5 U21.6 | length 335.1
  Top Signal w5.91: RJ2.8@658.6,976.57 658.6,1055.11 673.3,1069.81 673.3,1079.07 700.47,1106.24 700.47,1132.17 719.42,1151.11 719.42,1163.59 715.63,1167.38 715.63,1181.75 719.57,1185.69 719.57,1196.31 715.63,1200.25 U21.5@715.63,1207.44 715.63,1214.62 719.57,1218.56 719.57,1233.88 730.94,1245.25 730.94,1262.88 727,1266.82 U20.4@727,1273.71
PHY1_RD_P: C110.1 RJ2.7 U20.5 U21.4 U21.7 | length 397.1
  Top Signal w5.91: RJ2.7@698.76,976.57 698.76,1055.11 684.21,1069.66 684.21,1074.56 v1(730.77,1121.12) 730.77,1125.47 724.05,1132.2 724.05,1140.32 730.32,1146.6 730.32,1162.93 733.78,1166.39 734.33,1166.39 735.32,1167.38 735.32,1181.75 731.38,1185.69 731.38,1196.31 735.32,1200.25 U21.4@735.32,1207.44 735.32,1214.62 731.38,1218.56 731.38,1228.98 742.75,1240.35 742.75,1262.88 746.69,1266.82 U20.5@746.69,1273.71
  Bottom Signal w5.91: v1(730.77,1121.12) 748.65,1139 C110.1@748.65,1169.35
PHY1_TD_N: C107.1 RJ2.4 U20.6 U21.2 U21.9 | length 388.1
  Top Signal w5.91: U20.6@766.37,1273.71 766.37,1266.82 770.31,1262.88 770.31,1245.74 778.62,1237.43 778.62,1218.56 774.69,1214.62 U21.2@774.69,1207.44 774.69,1200.25 778.62,1196.31 778.62,1185.69 774.69,1181.75 774.69,1167.38 775.67,1166.39 776.2,1166.39 779.66,1162.93 779.66,1148.06 779.66,1130.76 833.41,1077.01 833.41,1067.62 829.95,1064.17 828.29,1064.17 819.23,1055.11 RJ2.4@819.23,976.57
  Bottom Signal w5.91: v1(783.72,1126.65) 784.41,1125.96 831.95,1125.96 C107.1@832.64,1125.27
PHY1_TD_P: C108.1 RJ2.3 U20.7 U21.1 U21.10 | length 331
  Top Signal w5.91: U20.7@786.06,1273.71 786.06,1266.82 782.12,1262.88 782.12,1250.64 790.43,1242.32 790.43,1218.56 794.37,1214.62 U21.1@794.37,1207.44 794.37,1200.25 790.43,1196.31 790.43,1185.69 U21.10@794.37,1181.75 ; U21.10@794.37,1174.56 794.37,1167.38 790.57,1163.57 790.57,1151.52 800.82,1141.26 C108.1@807.7,1134.38 ; C108.1@807.71,1134.36 807.71,1118.14 844.31,1081.53 844.31,1068.53 848.68,1064.17 850.34,1064.17 859.39,1055.11 RJ2.3@859.39,976.57
QEP1_SEL: S5.5 U14.9 U14.10 U14.11 | length 428.3
  Top Signal w4: v1(1279,2487) 1299.09,2466.91 1324.16,2441.84 U14.9@1324.16,2416.05 U14.10@1324.16,2390.46 U14.11@1324.16,2364.87
  Top Signal w5: S5.5@1132.57,2679.53 v1(1188.99,2679.53)
  Bottom Signal w4: v1(1188.99,2679.53) 1188.99,2675.17 1280.43,2583.73 1280.43,2488.43 v1(1279,2487)
QEP2_SEL: S5.2 U11.9 U11.10 U11.11 | length 607.4
  Top Signal w5: U11.11@949.11,2364.87 954.64,2370.4 981.43,2370.4 984.36,2373.33 984.36,2382 981.43,2384.93 954.64,2384.93 942.75,2396.82 917.94,2396.82 915.01,2399.75 915.01,2406.76 917.94,2409.69 942.75,2409.69 U11.9@949.11,2416.05 1014.76,2416.05 S5.2@1278.24,2679.53
SCI_SEL1: S2.2 U6.1 U6.5 U9.1 U9.5 | length 975.1
  Top Signal w11.81: U6.5@752.14,5182.29 797.29,5182.29 815.07,5200.07 815.07,5245.83 799.86,5261.03 U6.1@752.14,5261.03 ; v1(921.56,5004.64) S2.2@977.96,5004.64 ; U9.1@1098.81,5223.29 v1(1098.81,5156.03) 1163.13,5156.03 1177.55,5170.45 U9.5@1177.55,5223.29
  Bottom Signal w11.81: v1(815.27,5201.98) 815.27,5065.99 876.62,5004.64 v1(921.56,5004.64) 983.28,5004.64 1098.81,5120.17 v1(1098.81,5156.03)
SCI_SEL2: S2.5 U8.1 U8.5 | length 489.4
  Top Signal w12: S2.5@1123.63,5004.64 1129.73,5010.74 1166.1,5010.74 1249.88,5094.52 1249.88,5162.11 1270.06,5182.29 U8.5@1299.4,5182.29 1350.82,5182.29 1370.24,5201.71 1370.24,5246.35 1355.55,5261.03 U8.1@1299.4,5261.03
USB_CC1: R78.2 U16.4 U16.7 USB1.A5 | length 317.1
  Top Signal w6: R78.2@400.37,6226.02 400.37,6264.04 418.27,6281.94 487.59,6281.94 524.52,6318.86 U16.4@524.52,6345.49 U16.7@524.52,6378.36 524.52,6409.73 506.15,6428.11 506.15,6443.01 USB1.A5@505.82,6443.34
USB_CC2: R81.2 U16.5 U16.6 USB1.B5 | length 596.6
  Top Signal w6: R81.2@458.85,6230.59 458.85,6253.54 476.69,6271.37 494.72,6271.37 544.2,6320.86 544.2,6385.55 545.14,6386.49 545.27,6386.49 549.49,6390.71 v1(565.82,6390.71)
  Top Signal w12: v4@455.7,6483.69 USB1.B5@455.7,6514.21
  Middle Signal w12: v4(456,6483.39) 421.92,6483.39 379.05,6440.51 379.05,6395.12 398.77,6375.39 548.87,6375.39 564.19,6390.71 v1(565.82,6390.71)
USB_D_N: U2.93 U16.1 U16.10 USB1.A7 USB1.B7 | length 2066.3
  Top Signal w10.63: v1(463.67,6315.36) 465.46,6317.15 U16.1@465.46,6345.49 465.46,6409.98 v1(463.67,6411.77) 465.54,6413.64 USB1.A7@465.54,6451.22 ; USB1.B7@495.07,6514.21 495.07,6494.56 504.01,6485.62 v4(504.01,6484.23) ; v1(1821.48,6402) 1823.9,6404.43 1823.9,6428.22 1892.17,6496.49 U2.93@2003.34,6496.49
  Middle Signal w10.63: v1(463.67,6315.36) 470.27,6308.77 470.27,6264.49 601.35,6133.41 1353.78,6133.41 1597.38,6377.01 1781.89,6377.01 1805.76,6400.88 1820.35,6400.88 v1(1821.48,6402)
  Bottom Signal w10.63: v1(463.67,6411.77) 504.01,6452.11 v4(504.01,6484.23)
USB_D_P: U2.94 U16.2 U16.9 USB1.A6 USB1.B6 | length 1975.3
  Top Signal w10.63: USB1.B6@475.39,6514.21 475.39,6484.02 485.23,6474.18 USB1.A6@485.23,6451.22 485.23,6359.14 485.15,6359.06 485.15,6345.57 485.23,6345.49 485.23,6323.41 v1(493.49,6315.14) ; v1(1802.55,6430.39) 1884.4,6512.24 U2.94@2003.34,6512.24
  Middle Signal w10.63: v1(493.49,6315.14) 486.9,6308.54 486.9,6271.38 608.24,6150.04 1346.89,6150.04 1585.62,6388.77 1590.49,6393.64 1775.01,6393.64 1800.38,6419.01 1800.38,6428.22 v1(1802.55,6430.39)
USB_GND: C80.1 C126.2 C127.2 C128.2 C129.2 C131.1 C132.2 C134.1 C135.1 C136.1 C137.1 C138.1 C139.2 C140.2 C141.1 C142.2 C143.1 C144.2 C145.1 C146.2 C147.2 JP1.3 LED1.1 LED7.1 LED8.2 LED9.2 R68.1 R78.1 R81.1 R175.1 R176.1 U2.10 U2.17 U2.48 U2.55 U2.58 U2.64 U2.66 U2.80 U2.114 U16.3@504.83,6345.49 U16.8@504.83,6378.36 U25.2 U25.4 U26.2 U26.8 U27.2 U27.8 USB1.1 USB1.2 USB1.3 USB1.4 USB1.A1 USB1.A12 USB1.B1 USB1.B12 Y1.2 Y1.4 | length 334.6
  Top Signal w7.87: v1(1345,6293) 1346.23,6291.77 U2.17@1397.04,6291.77 ; U2.114@1676.57,6602.79 v1(1676.57,6649.64) ; U2.48@1692.32,5996.49 1692.32,6027.63 v1(1706.65,6041.97) ; v1(1960.98,6071.3) U2.66@2003.34,6071.3
  Top Signal w11.81: U16.8@504.83,6381.47 505.66,6382.3 U16.8@505.03,6382.93 ; U16.3@505.03,6347.93 v1@505.03,6399.49
  Top Signal w15: U2.55@1802.55,5996.49 v1(1802.55,6041.97) ; U2.58@1849.8,5996.49 v1(1849.8,6038.86)
  other v1: 345.59,5869.52 1740.62,5873.4 1687,5907 693.65,5917.14 2203.01,5932.39 487.44,5935.85 1705.7,5944.1 1965.27,5961.97 416.33,5992.14 286.29,5995.51 2014.52,6034.56 1944.28,6038.86 338.85,6077.36 2221.53,6092.95 1031,6095.78 1275.5,6095.78 1582.28,6095.78 263.02,6106.06 202.75,6108.39 544.99,6126.39 400.37,6130.75 1830.54,6132.79 1514.56,6134.64 69.48,6137.83 348.02,6163.54 159.68,6166.89 503.5,6168.03 706.02,6171.39 939,6182.32 1705.7,6182.32 1903.54,6182.32 821.49,6196.89 1146.63,6196.89 778.5,6207.83 1818.1,6220.9 1735.7,6226.69 345.74,6227.87 1518.89,6233.58 2188.74,6235.22 74.48,6238.7 2140.17,6240.14 759.34,6265.14 1629.32,6265.14 2061.41,6290.25 152.71,6292.2 2091.91,6293 2148.69,6303.43 1914.99,6307.12 2217.9,6307.12 299.86,6328.14 1827.17,6342.73 1148.69,6345.04 1914.99,6354.41 803.33,6377.01 295.36,6378.36 1538.28,6382.1 505.4,6403.82 633.68,6410.63 583.65,6416.77 1883.6,6417.75 336.36,6418.7 1329.06,6424.39 743.57,6430.27 1555.4,6431.08 1608.57,6432.96 1757.98,6439.21 1074.2,6447.16 1665.29,6456.84 1709.99,6464.79 950.19,6490.15 2053.26,6491.14 768.4,6499.22 2211.69,6515.73 1838.41,6517.63 1328.93,6527.99 74.48,6540.76 1470.58,6541.45 2159.5,6547.22 1772.16,6552.99 2232.35,6554.45 1085.5,6555.75 1324.28,6656.21 939,6657 1239.72,6656.89 1146.63,6661.02 1913.97,6683.57 188.73,6688.25 1443.22,6692.63 1720.19,6698.78 2102.91,6701.97
VDD: C54.1 C55.1 C56.1 C57.1 C58.1 C74.2 C75.2 JP4.1 L1.2 TP1.1 U1.F5 U1.F7 U1.G9 U1.J9 U10.1 | length 959.3
  Top Signal w10: U1.J9@1149.95,3748.31 v2(1168.05,3748.31) ; U1.F7@1168.05,3838.79 v2(1186.14,3838.79) ; v2(1186.14,3766.4) U1.G9@1186.14,3784.5
  Top Signal w11.81: U1.F5@1131.86,3874.98 v2(1149.95,3874.98)
  Bottom Signal w10: L1.2@1049.74,4116.41 1049.74,4121.78 1085.56,4157.6 1105.02,4157.6 v1@1105.42,4158 ; v1(1101.62,4130.89) 1099.33,4128.59 1099.33,4109.02 1089.74,4099.44 C54.1@1089.74,4057.11 1117.04,4029.82 C56.1@1150.58,4029.82 ; v2(1168.05,3748.31) v2(1186.14,3766.4) 1223.94,3766.4 1250.35,3740 1284.99,3740 1302.36,3722.62 C58.1@1302.82,3722.62 1268.2,3688.01 C57.1@1267.71,3688.01 ; v2(1186.14,3838.79) 1186.14,3864.36 C55.1@1253.51,3931.73 ; U10.1@1952.41,3874.68 1952.45,3874.64 JP4.1@2049.99,3874.64 ; C74.2@2052.6,3789.84 2052.6,3872.04 2050.45,3874.18 2097.21,3874.18 2135.13,3836.27 C75.2@2135.13,3790.16
  other v1: 1101.62,4158
VDDA: C61.1 C62.1 L2.2 TP3.1 U1.L2 U1.M5 | length 333.9
  Top Signal w10: v2(969,3838.79) U1.L2@987.09,3838.79 ; v2(1005.19,3766.4) U1.M5@1023.28,3766.4
  Bottom Signal w10: v1(684.87,3678.95) 707.14,3656.68 L2.2@707.14,3575.24 ; C61.1@901.18,3870.8 933.2,3838.79 v2(969,3838.79) ; C62.1@923.45,3711.11 924.15,3711.81 950.59,3711.81 v2@1004.52,3765.74
VDDIO: C65.1 C66.1 C67.1 C68.1 C69.1 C70.1 C71.1 C72.1 C73.1 L3.2 TP2.1 U1.C13 U1.E11 U1.F4 U1.F6 U1.F8 U1.H9 U1.J8 U1.M8 | length 793.7
  Top Signal w10: v2(1077.57,3694.02) U1.M8@1077.57,3712.12 ; U1.F4@1113.76,3893.07 v2(1113.76,3911.17) ; v2(1113.76,3766.4) U1.J8@1131.86,3766.4 ; v2(1131.86,3856.88) U1.F6@1149.95,3856.88 ; v2(1149.95,3766.4) U1.H9@1168.05,3766.4 ; U1.F8@1186.14,3820.69 v2(1204.24,3820.69) ; U1.E11@1258.52,3784.5 v2(1276.62,3784.5) ; U1.C13@1330.9,3784.5 v2(1330.9,3802.59)
  Bottom Signal w10: v1@960.79,3994.44 960.79,3998.71 C68.1@980.57,4018.49 ; C67.1@964.75,3676.16 974.39,3676.16 974.39,3678.95 995.31,3699.87 v1(998.56,3699.87) ; C70.1@1049.91,3667.4 C70.1@1050.94,3667.4 ; C72.1@1054.13,3944.93 1087.89,3911.17 v2(1113.76,3911.17) ; C70.1@1056.91,3664.06 1076.8,3683.95 1076.8,3693.26 v2(1077.57,3694.02) ; C69.1@1057.22,3766.64 1060,3769.43 1069.63,3769.43 1072.42,3766.64 1113.52,3766.64 v2(1113.76,3766.4) v2(1149.95,3766.4) ; L3.2@1101.57,3591.36 1114.31,3578.62 v1(1114.31,3531.44) ; v2(1276.62,3784.5) 1310.34,3784.5 C71.1@1337.27,3757.57 ; v2(1330.9,3802.59) 1366.68,3802.59 C73.1@1396.03,3773.24 1402.35,3773.24 C65.1@1438.72,3736.87 ; C66.1@1402.12,3866.86 1478.36,3866.86 TP2.1@1488.86,3877.37
  other v1: 960.46,3998.17
VREFHI: C13.1 C14.1 C15.1 J15.1 U1.J2 U1.K2 U1.M4 | length 933.8
  Top Signal w4: 920.15,3905.71 942.72,3905.71 971.02,3877.4 971.02,3872.1 986.04,3857.08 U1.K2@1005.19,3856.88 U1.J2@1023.28,3874.98
  Top Signal w5: v2(987.09,3784.5) U1.M4@1005.19,3784.5
  Top Signal w12: v1(851.4,3974.46) 920.15,3905.71
  PWR w12: v1(851.4,3974.46) 851.4,3844.09 910.98,3784.5 v2(987.09,3784.5)
  Bottom Signal w12: C13.1@690.83,3826.06 690.83,3889.45 J15.1@673.14,3907.14 723.79,3957.78 C15.1@779.4,3957.78 796.08,3974.46 v1(851.4,3974.46) ; C14.1@894.75,3767.66 C14.1@898.91,3771.81 911.59,3784.5 v2(987.09,3784.5)
VREGENZ: R47.1 R53.2 U1.E10 | length 830.8
  Top Signal w11.81: U1.E10@1240.43,3802.59 v2(1258.52,3802.59)
  Middle Signal w4: v2(1258.52,3802.59) 1276.62,3802.59 1324.24,3754.97
  Middle Signal w11.81: 1324.24,3754.97 1373.33,3705.88 v1(1398.57,3705.88)
  PWR w11.81: v1(1398.57,3705.88) 1417.34,3724.66 1442.15,3724.66 1731,4013.51 1731,4062.83 v1(1745.6,4077.43) v1(1774.02,4077.43)
  Bottom Signal w11.81: v1(1745.6,4077.43) 1747.55,4075.48 1747.55,4070.6 1772.07,4046.08 R47.1@1773.05,4046.08 ; R53.2@1773.06,4108.08 1774.02,4107.11 v1(1774.02,4077.43)
X1: R20.2 U1.D13 | length 600.3
  Top Signal w4: U1.D13@1312.81,3766.4 1399.26,3679.96 1443.99,3679.96 v1@1461.6,3662.35
  Top Signal w5: R20.2@1595.83,3440.39 1597.71,3442.27 1597.71,3559.78 1634.48,3596.54 v1(1634.48,3642.52)
  Bottom Signal w5: v1(1455.25,3669.23) 1473.16,3651.32 1622.86,3651.32 1631.66,3642.52 v1(1634.48,3642.52)
XDS_RESET_INT: J101.10 U5.1 U27.14 | length 638.7
  Top Signal w5: v1(1068.17,5493.8) 1068.69,5494.32 1068.69,5515.46 U5.1@1069.21,5515.98 ; U27.14@1176.45,5606.07 1176.45,5508.64 v1(1175.17,5507.35) 1182.82,5499.71 1316.06,5499.71 1368.02,5551.67 1478.37,5551.67 1488.46,5541.58 J101.10@1488.46,5479.49
  Middle Signal w5: v1(1068.17,5493.8) 1081.72,5507.35 v1(1175.17,5507.35)
XDS_RESET_OUT: R16.1 U2.40 U27.3 | length 538.1
  Top Signal w6: v1(1561.06,5950.51) 1585.35,5926.22 R16.1@1609.46,5926.22 ; v1@1566.32,5955.76 U2.40@1566.33,5996.49
  Top Signal w7.87: v1(1176.45,5945.26) U27.3@1176.45,5989.93
  Middle Signal w6: v1(1176.45,5945.26) 1555.81,5945.26 v1(1561.06,5950.51) v1@1566.32,5955.76
XDS_RXD: U2.33 U27.5 | length 503.2
  Top Signal w6: U27.5@1076.45,5989.93 1076.45,6030.7 1093.8,6048.04 1330.23,6048.04 1422.52,5955.76 1450.39,5955.76 1456.09,5961.47 U2.33@1456.09,5996.49
XDS_TCK_SWDCLK: U2.35 U26.4 | length 892.3
  Top Signal w6: U2.35@1487.59,5996.49 v1(1487.59,6034.56)
  Top Signal w7.87: U26.4@688.77,5989.93 v1(688.77,6042.19)
  Middle Signal w6: v1(688.77,6042.19) 1475.63,6042.19 1483.26,6034.56 v1(1487.59,6034.56)
XDS_TDI: U2.38 U26.5 | length 997.9
  Top Signal w6: v1(1487.49,6066.06) 1489.37,6064.18 1495.17,6064.18 1534.83,6024.52 U2.38@1534.83,5996.49
  Top Signal w7.87: U26.5@638.77,5989.93 642.43,5993.59 642.43,6036.42 v1(670.41,6064.4)
  Middle Signal w6: v1(670.41,6064.4) 1485.83,6064.4 v1(1487.49,6066.06)
XDS_TDO_SWO: U2.37 U26.6 | length 1072.2
  Top Signal w6: U26.6@588.77,5989.93 588.77,5953.51 661.41,5880.87 1450.35,5880.87 1519.09,5949.61 U2.37@1519.09,5996.49
XDS_TMS_SWDIO: U2.36 U26.3 | length 896
  Top Signal w6: U26.3@738.77,5989.93 738.77,5953.51 797.84,5894.44 1449.5,5894.44 1503.34,5948.28 U2.36@1503.34,5996.49
XDS_TXD: U2.34 U27.4 | length 471
  Top Signal w6: U27.4@1126.45,5989.93 1126.79,5990.26 1126.79,6029.61 1133.35,6036.17 1319.4,6036.17 1414.36,5941.21 1452.46,5941.21 1455.13,5943.88 1455.3,5943.88 1471.84,5960.42 U2.34@1471.84,5996.49
XRSn: C28.1 J4/J2.16 J8/J6.56 R59.1 R95.1 S1.4 U1.D12 | length 4326.6
  Top Signal w4: U1.D12@1294.71,3784.5 1294.71,3767.66 1311.14,3751.23 1390.42,3671.96 1419.97,3671.96 1440.59,3651.33 1472.62,3651.33 1490.51,3669.23 v1(1494.25,3669.23)
  Top Signal w5: S1.4@2150.08,5604.97 S1.4@2152.43,5607.32
  Top Signal w6: J4/J2.16@2049.99,4874.64 2093.65,4918.3 2093.65,5516.55 2152.43,5575.33 S1.4@2152.43,5607.32
  Bottom Signal w5: v1@1496.11,3669.23 1730.52,3669.23 1812.46,3587.3 R95.1@1938.83,3587.3 2009.89,3587.3 R59.1@2017.76,3595.17 ; R59.1@2014.86,3587.3 2076.21,3587.3 C28.1@2084.09,3595.17 2147,3532.26 2147,2471.65 J8/J6.56@2049.99,2374.64 ; J4/J2.16@2049.99,4874.64 2165.24,4759.39 2165.24,3676.33 C28.1@2086.05,3597.14
pads on no net: B1.7 FID1.1 FID2.1 FID3.1 FID4.1 FID5.1 FID6.1 J11.9 J101.7 M1.0 M2.0 M3.0 M4.0 M5.0 M6.0 M7.0 MH1.1 MH2.1 MH3.1 MH4.1 RJ1.9 RJ1.ALIGN1 RJ1.ALIGN2 RJ2.9 RJ2.ALIGN1 RJ2.ALIGN2 S1. U1.E13 U1.H3 U1.H4 U1.H5 U1.J3 U1.J5 U1.K3 U1.K6 U1.L6 U1.M3 U1.N6 U2.1 U2.2 U2.5 U2.6 U2.11 U2.12 U2.13 U2.14 U2.15 U2.18 U2.19 U2.20 U2.21 U2.22 U2.23 U2.24 U2.25 U2.27 U2.29 U2.30 U2.31 U2.32 U2.41 U2.42 U2.43 U2.44 U2.45 U2.46 U2.49 U2.50 U2.53 U2.54 U2.56 U2.57 U2.65 U2.67 U2.71 U2.72 U2.73 U2.74 U2.75 U2.76 U2.77 U2.78 U2.81 U2.82 U2.83 U2.84 U2.85 U2.86 U2.91 U2.92 U2.95 U2.97 U2.98 U2.99 U2.100 U2.102 U2.103 U2.104 U2.105 U2.106 U2.107 U2.108 U2.109 U2.110 U2.111 U2.112 U2.116 U2.117 U2.118 U2.119 U2.120 U2.121 U2.123 U2.124 U2.125 U2.126 U2.127 U2.128 U5.2 U10.6 U15.5 U15.8 U16.3@504.83,6345.49 U16.8@504.83,6378.36 U17.1 U17.8 U17.33@1578.55,1345.76 U17.33@1578.55,1390.64 U17.33@1623.43,1345.76 U17.33@1623.43,1390.64 U19.3@1620.99,1207.44 U19.8@1620.99,1174.56 U20.1 U20.8 U20.33@714.4,1345.76 U20.33@714.4,1390.64 U20.33@759.28,1345.76 U20.33@759.28,1390.64 U21.3@755,1207.44 U21.8@755,1174.56 U22.5 U27.6 U27.11 USB1.A2 USB1.A3 USB1.A8 USB1.A10 USB1.A11 USB1.B2 USB1.B3 USB1.B8 USB1.B10 USB1.B11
